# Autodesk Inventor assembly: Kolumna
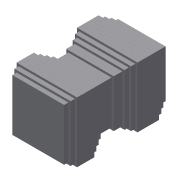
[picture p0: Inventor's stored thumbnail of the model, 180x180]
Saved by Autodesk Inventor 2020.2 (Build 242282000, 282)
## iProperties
Manager: www.cadconsulting.pl
Company: Fabian Stasiak CAD Consulting
Created: 2005-11
Part Number: Kolumna
Document SubType Name: Assembly
Designer: F.Stasiak
Author: F.Stasiak
Subject: Zbiór ćwiczeń. Autodesk Inventor 2020. Kurs podstawowy
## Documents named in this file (6)
- C:\2020_Kurs_podstawowy\R6 Zespoły\Elementy\Kolumna.iam
- C:\2020_Kurs_podstawowy\R6 Zespoły\Elementy\P1.ipt
- C:\2020_Kurs_podstawowy\R6 Zespoły\Elementy\P2.ipt
- C:\2020_Kurs_podstawowy\R6 Zespoły\Elementy\P3.ipt
- C:\2020_Kurs_podstawowy\R6 Zespoły\Elementy\P5.ipt
- C:\2020_Kurs_podstawowy\R6 Zespoły\Elementy\P6.ipt
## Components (24 placed, 5 different names)
1. P1:1 — Równoległy:1
2. P2:1 — Równoległy:1, Równoległy:2, Zestawiający:20, Równoległy:20
3. P3:1 — Równoległy:2, Zestawiający:21, Równoległy:21, Zestawiający:25, Równoległy:47, Równoległy:48
4. P3:2 — Zestawiający:2, Równoległy:4, Równoległy:5
5. P3:3 — Zestawiający:2, Równoległy:4, Równoległy:5, Zestawiający:3, Równoległy:23, Równoległy:24
6. P2:2 — Zestawiający:3, Zestawiający:4, Równoległy:25, Równoległy:26
7. P1:2 — Zestawiający:4, Równoległy:6, Równoległy:27, Równoległy:28
8. P5:1 — Równoległy:6, Równoległy:7, Równoległy:29, Zestawiający:23
9. P6:1 — Równoległy:7, Zestawiający:5, Równoległy:8, Równoległy:9, Zestawiający:24, Równoległy:30
10. P6:2 — Zestawiający:5, Równoległy:8, Równoległy:9, Zestawiający:6, Równoległy:10, Równoległy:11
11. P6:3 — Zestawiający:6, Równoległy:10, Równoległy:11, Zestawiający:7
12. P5:2 — Zestawiający:7, Zestawiający:8, Równoległy:31, Równoległy:32, Równoległy:33, Równoległy:34
13. P5:3 — Zestawiający:8, Zestawiający:9, Równoległy:33, Równoległy:34
14. P1:3 — Zestawiający:9, Zestawiający:10, Równoległy:35, Równoległy:36
15. P2:3 — Zestawiający:10, Zestawiający:11, Równoległy:37, Równoległy:38
16. P3:4 — Zestawiający:11, Zestawiający:12, Równoległy:12, Równoległy:13, Równoległy:39, Równoległy:40
17. P3:5 — Zestawiający:12, Równoległy:12, Równoległy:13, Zestawiający:13, Równoległy:14, Równoległy:15
18. P3:6 — Zestawiający:13, Równoległy:14, Równoległy:15, Zestawiający:14, Równoległy:16, Równoległy:17, Równoległy:18
19. P3:7 — Zestawiający:14, Równoległy:16, Równoległy:17, Zestawiający:15, Równoległy:19
20. P3:8 — Zestawiający:15, Równoległy:18, Równoległy:19, Zestawiający:16
21. P2:4 — Zestawiający:16, Zestawiający:17, Równoległy:41, Równoległy:42
22. P1:4 — Zestawiający:17, Zestawiający:18, Równoległy:43, Równoległy:44
23. P5:4 — Zestawiający:18, Równoległy:45, Równoległy:46
24. P3:9 — Zestawiający:25, Równoległy:47, Równoległy:48
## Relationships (68: Flush 46, Mate 22)
- Równoległy:1 [Flush]: P1:1 ↔ P2:1
- Równoległy:2 [Flush]: P2:1 ↔ P3:1
- Zestawiający:2 [Mate]: P3:2 ↔ P3:3
- Równoległy:4 [Flush]: P3:2 ↔ P3:3
- Równoległy:5 [Flush]: P3:2 ↔ P3:3
- Zestawiający:3 [Mate]: P3:3 ↔ P2:2
- Zestawiający:4 [Mate]: P2:2 ↔ P1:2
- Równoległy:6 [Flush]: P1:2 ↔ P5:1
- Równoległy:7 [Flush]: P5:1 ↔ P6:1
- Zestawiający:5 [Mate]: P6:1 ↔ P6:2
- Równoległy:8 [Flush]: P6:1 ↔ P6:2
- Równoległy:9 [Flush]: P6:1 ↔ P6:2
- Zestawiający:6 [Mate]: P6:2 ↔ P6:3
- Równoległy:10 [Flush]: P6:2 ↔ P6:3
- Równoległy:11 [Flush]: P6:2 ↔ P6:3
- Zestawiający:7 [Mate]: P6:3 ↔ P5:2
- Zestawiający:8 [Mate]: P5:2 ↔ P5:3
- Zestawiający:9 [Mate]: P5:3 ↔ P1:3
- Zestawiający:10 [Mate]: P1:3 ↔ P2:3
- Zestawiający:11 [Mate]: P2:3 ↔ P3:4
- Zestawiający:12 [Mate]: P3:4 ↔ P3:5
- Równoległy:12 [Flush]: P3:4 ↔ P3:5
- Równoległy:13 [Flush]: P3:4 ↔ P3:5
- Zestawiający:13 [Mate]: P3:5 ↔ P3:6
- Równoległy:14 [Flush]: P3:5 ↔ P3:6
- Równoległy:15 [Flush]: P3:5 ↔ P3:6
- Zestawiający:14 [Mate]: P3:6 ↔ P3:7
- Równoległy:16 [Flush]: P3:6 ↔ P3:7
- Równoległy:17 [Flush]: P3:6 ↔ P3:7
- Zestawiający:15 [Mate]: P3:7 ↔ P3:8
- Równoległy:18 [Flush]: P3:6 ↔ P3:8
- Równoległy:19 [Flush]: P3:7 ↔ P3:8
- Zestawiający:16 [Mate]: P3:8 ↔ P2:4
- Zestawiający:17 [Mate]: P2:4 ↔ P1:4
- Zestawiający:18 [Mate]: P1:4 ↔ P5:4
- Zestawiający:20 [Mate]: P2:1
- Równoległy:20 [Flush]: P2:1
- Zestawiający:21 [Mate]: P3:1
- Równoległy:21 [Flush]: P3:1
- Równoległy:23 [Flush]: P3:3
- Równoległy:24 [Flush]: P3:3
- Równoległy:25 [Flush]: P2:2
- Równoległy:26 [Flush]: P2:2
- Równoległy:27 [Flush]: P1:2
- Równoległy:28 [Flush]: P1:2
- Równoległy:29 [Flush]: P5:1
- Zestawiający:23 [Mate]: P5:1
- Zestawiający:24 [Mate]: P6:1
- Równoległy:30 [Flush]: P6:1
- Równoległy:31 [Flush]: P5:2
- Równoległy:32 [Flush]: P5:2
- Równoległy:33 [Flush]: P5:2 ↔ P5:3
- Równoległy:34 [Flush]: P5:2 ↔ P5:3
- Równoległy:35 [Flush]: P1:3
- Równoległy:36 [Flush]: P1:3
- Równoległy:37 [Flush]: P2:3
- Równoległy:38 [Flush]: P2:3
- Równoległy:39 [Flush]: P3:4
- Równoległy:40 [Flush]: P3:4
- Równoległy:41 [Flush]: P2:4
- Równoległy:42 [Flush]: P2:4
- Równoległy:43 [Flush]: P1:4
- Równoległy:44 [Flush]: P1:4
- Równoległy:45 [Flush]: P5:4
- Równoległy:46 [Flush]: P5:4
- Zestawiający:25 [Mate]: P3:1 ↔ P3:9
- Równoległy:47 [Flush]: P3:1 ↔ P3:9
- Równoległy:48 [Flush]: P3:1 ↔ P3:9
